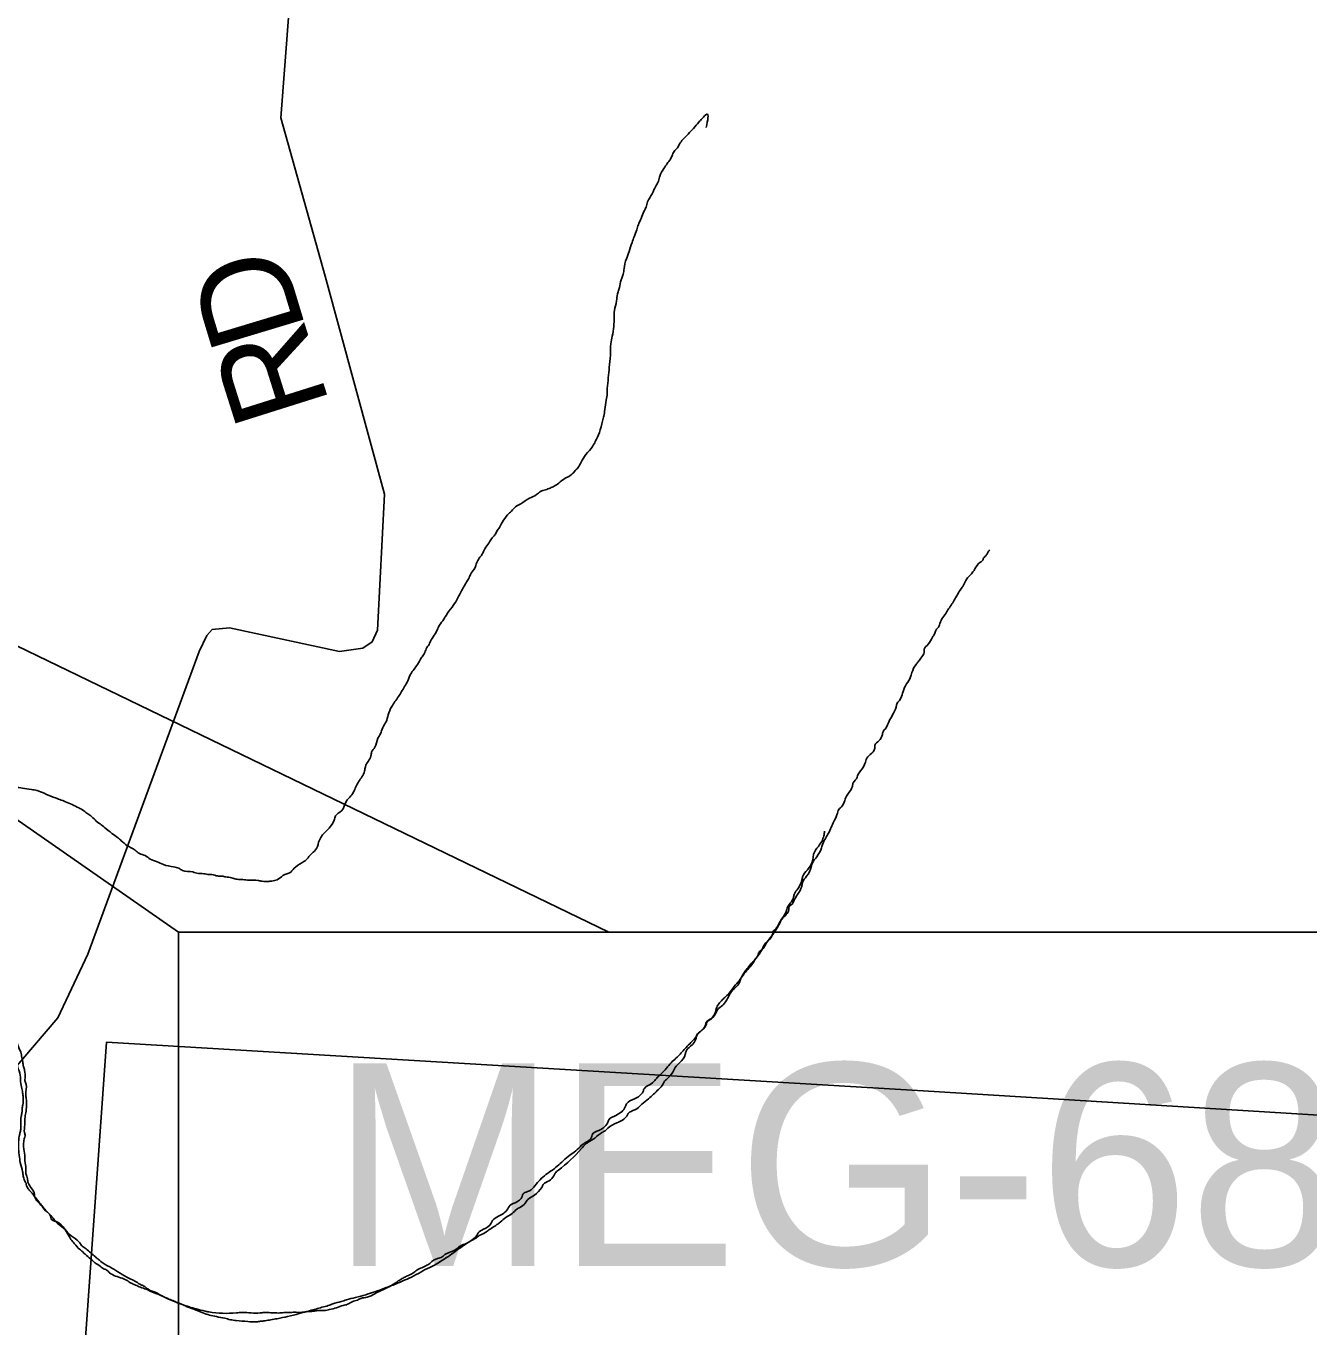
# Model space of a CAD drawing. Extents: x -15 to 405, y -40 to 87.
# Drawn here: x 5.103 to 5.862, y 16.636 to 17.407 of the extents above; entities that cross this region are included whole.
import ezdxf

# ---------------------------------------------------------------- set-up
doc = ezdxf.new("R2010")
doc.units = 0
for name, color, linetype in [('GM_P_State_Location', 7, 'Continuous'), ('GM_X_Adjacent_County', 7, 'Continuous'), ('GM_X_Adjacent_County_Text', 7, 'Continuous'), ('GM_X_Airport_Location_Class_2', 7, 'Continuous'), ('GM_X_Minor_River', 7, 'Continuous'), ('GM_X_Township', 7, 'Continuous')]:
    doc.layers.add(name, color=color, linetype=linetype)

msp = doc.modelspace()

# ---------------------------------------------------------------- linework, layer by layer
at = {"layer": 'GM_P_State_Location'}
msp.add_lwpolyline([(4.89566, 16.45119), (4.92556, 16.51497), (5.0014, 16.68063), (5.04391, 16.72434), (5.0716, 16.7612), (5.12131, 16.81934), (5.13914, 16.85696), (5.2051, 17.03628), (5.20965, 17.04578), (5.21268, 17.0492), (5.22294, 17.05035), (5.28827, 17.03633), (5.30193, 17.03824), (5.30763, 17.04204), (5.31066, 17.04888), (5.31479, 17.12941), (5.27976, 17.25853), (5.2535, 17.35234), (5.25839, 17.41691)], dxfattribs=at)
at = {"layer": 'GM_X_Adjacent_County'}
for points in [[(5.19285, 16.86992), (4.61361, 17.27343), (5.44781, 16.86992)], [(5.19285, 16.58992), (6.44286, 16.58992), (6.44286, 16.86992), (5.19285, 16.86992)]]:
    msp.add_lwpolyline(points, close=True, dxfattribs=at)
at = {"layer": 'GM_X_Adjacent_County_Text'}
for points in [[(5.32873, 17.01885), (5.33038, 17.02297), (5.33436, 17.02854), (5.33677, 17.03264), (5.33837, 17.03487), (5.33961, 17.03787), (5.34121, 17.04047), (5.34244, 17.04309), (5.34484, 17.04681), (5.34605, 17.04905), (5.34728, 17.05167), (5.35005, 17.05538), (5.35127, 17.05762), (5.35484, 17.06244), (5.35765, 17.06691), (5.35927, 17.06989), (5.36169, 17.07437), (5.3637, 17.07773), (5.36491, 17.07996), (5.36614, 17.08258), (5.36853, 17.08592), (5.36938, 17.08856), (5.37099, 17.09154), (5.37258, 17.09377), (5.37421, 17.09714), (5.3766, 17.10048), (5.37821, 17.10308), (5.38018, 17.1053), (5.38139, 17.10754), (5.38298, 17.10976), (5.3846, 17.11275), (5.38779, 17.1172), (5.39013, 17.11941), (5.3925, 17.12199), (5.39559, 17.12378), (5.40064, 17.12704), (5.40488, 17.12918), (5.40722, 17.131), (5.41029, 17.13204), (5.41299, 17.13309), (5.4153, 17.13415), (5.41802, 17.13596), (5.42191, 17.13887), (5.42461, 17.1403), (5.42735, 17.14287), (5.42933, 17.14509), (5.43134, 17.14844), (5.43414, 17.15291), (5.43809, 17.15771), (5.43971, 17.1607), (5.44216, 17.16594), (5.44391, 17.17272), (5.44476, 17.17573), (5.44527, 17.17952), (5.44622, 17.18518), (5.44672, 17.18896), (5.44682, 17.192), (5.44741, 17.19844), (5.44799, 17.2045), (5.44861, 17.2117), (5.44884, 17.21853), (5.44975, 17.22306), (5.45088, 17.23442), (5.45101, 17.23822), (5.45234, 17.24388), (5.45285, 17.24804), (5.4537, 17.25067), (5.45461, 17.2552), (5.45627, 17.25971), (5.45677, 17.26311), (5.45809, 17.26876), (5.45976, 17.27327), (5.46145, 17.27853), (5.4627, 17.28191), (5.46436, 17.28603), (5.46522, 17.28904), (5.46686, 17.29279), (5.46852, 17.29692), (5.46974, 17.29953), (5.4706, 17.30254), (5.47342, 17.30739), (5.47546, 17.31188), (5.47708, 17.31487), (5.47794, 17.31788), (5.48037, 17.32236), (5.48236, 17.32533), (5.48396, 17.32756), (5.48517, 17.3298), (5.48639, 17.33242), (5.48837, 17.33463), (5.48958, 17.33687), (5.49156, 17.33947), (5.49785, 17.3461), (5.50101, 17.34979), (5.50299, 17.35201), (5.50573, 17.35458), (5.50546, 17.34661)], [(5.61988, 17.0073), (5.6211, 17.00954), (5.62237, 17.01368), (5.6248, 17.01815), (5.62683, 17.02227), (5.62726, 17.02377), (5.6297, 17.02863), (5.63089, 17.03011), (5.63248, 17.03234), (5.63449, 17.03569), (5.63455, 17.03759), (5.63693, 17.04055), (5.63934, 17.04465), (5.64054, 17.04651), (5.64138, 17.04876), (5.64336, 17.05136), (5.64379, 17.05286), (5.64781, 17.05957), (5.64941, 17.06218), (5.65141, 17.06515), (5.65222, 17.06664), (5.65382, 17.06925), (5.65583, 17.0726), (5.65742, 17.07483), (5.65985, 17.07931), (5.66143, 17.08116), (5.6634, 17.08337), (5.6646, 17.08523), (5.66738, 17.08894), (5.66893, 17.09003), (5.66974, 17.09152), (5.67132, 17.09337), (5.67213, 17.09486), (5.67332, 17.09634)], [(5.02697, 17.03113), (5.02759, 17.02693), (5.02782, 17.02236), (5.02913, 17.01624), (5.02907, 17.01434), (5.02969, 17.01014), (5.03002, 17.00861), (5.03064, 17.00441), (5.03097, 17.00288), (5.03159, 16.99868), (5.03153, 16.99678), (5.03181, 16.99373), (5.03241, 16.98915), (5.03236, 16.98763), (5.03303, 16.98495), (5.03366, 16.98113), (5.03355, 16.97772), (5.03417, 16.97351), (5.03412, 16.972), (5.03477, 16.96856), (5.03468, 16.9659), (5.03567, 16.96131), (5.03586, 16.9556), (5.03655, 16.95368), (5.03721, 16.95062), (5.03818, 16.94565), (5.0385, 16.94374), (5.03917, 16.94105), (5.03982, 16.93761), (5.04184, 16.92995), (5.04217, 16.92842), (5.04317, 16.9242), (5.0435, 16.92267), (5.04456, 16.92035), (5.0456, 16.91728), (5.04627, 16.9146), (5.04692, 16.91154), (5.04688, 16.91002), (5.04794, 16.9077), (5.0493, 16.9031), (5.04962, 16.90119), (5.05102, 16.89772), (5.05238, 16.89274), (5.05268, 16.89045), (5.05448, 16.88735), (5.05624, 16.88311), (5.05656, 16.88158), (5.05801, 16.87925), (5.05941, 16.87579), (5.06046, 16.87309), (5.06188, 16.87001), (5.06295, 16.86807), (5.06365, 16.86615), (5.06471, 16.86383), (5.06538, 16.86115), (5.06717, 16.85805), (5.06822, 16.85536), (5.07075, 16.85147), (5.07213, 16.84725), (5.0754, 16.84296), (5.07717, 16.8391), (5.08007, 16.83482), (5.08184, 16.83096), (5.08364, 16.82787), (5.08542, 16.82439), (5.08537, 16.82287), (5.08718, 16.82015), (5.08893, 16.81591), (5.08888, 16.81439), (5.09034, 16.81245), (5.09175, 16.80936), (5.09279, 16.80628), (5.09421, 16.8032), (5.09416, 16.80168), (5.09523, 16.79974), (5.09626, 16.79629), (5.0969, 16.79285), (5.09791, 16.78902), (5.09927, 16.78403), (5.09922, 16.78251), (5.09984, 16.77831), (5.10048, 16.77487), (5.10077, 16.7722), (5.10062, 16.76765), (5.10017, 16.76538), (5.10009, 16.76311), (5.09964, 16.76084), (5.09939, 16.75325), (5.09893, 16.75099), (5.09849, 16.7491), (5.0982, 16.74037), (5.09849, 16.7377), (5.09911, 16.7335), (5.10045, 16.72814), (5.10077, 16.72623), (5.10144, 16.72354), (5.1025, 16.72123)], [(5.03238, 16.98758), (5.0304, 16.9858), (5.03267, 16.98534), (5.03492, 16.98451), (5.03718, 16.98406), (5.03943, 16.98322), (5.04282, 16.98235), (5.04507, 16.98151), (5.04767, 16.97991), (5.05064, 16.97791), (5.05323, 16.97592), (5.05581, 16.97356), (5.06026, 16.97037), (5.06584, 16.96677), (5.06807, 16.96555), (5.07068, 16.96395), (5.07292, 16.96274), (5.07815, 16.96028), (5.0804, 16.95945), (5.08303, 16.9586), (5.08528, 16.95777), (5.08792, 16.9573), (5.09094, 16.95682), (5.0932, 16.95636), (5.09622, 16.95588), (5.10038, 16.95536), (5.10566, 16.95443), (5.10906, 16.95394), (5.11318, 16.95228), (5.11918, 16.9498), (5.12593, 16.9473), (5.13378, 16.94362), (5.13601, 16.9424), (5.13861, 16.94042), (5.14083, 16.93882), (5.14341, 16.93646), (5.14637, 16.93408), (5.14896, 16.9321), (5.1534, 16.92853), (5.15673, 16.92614), (5.15895, 16.92417), (5.16227, 16.92139), (5.16711, 16.91857), (5.1697, 16.91659), (5.17308, 16.91534), (5.17605, 16.91334), (5.18017, 16.91168), (5.18391, 16.91004), (5.18994, 16.9087), (5.19295, 16.90784), (5.19519, 16.90662), (5.20123, 16.90566), (5.20462, 16.90479), (5.20689, 16.90471), (5.21029, 16.90422), (5.21257, 16.90415), (5.21595, 16.90328), (5.21861, 16.90319), (5.22087, 16.90273), (5.22427, 16.90224), (5.2269, 16.90139), (5.22993, 16.90129), (5.23371, 16.90079), (5.24016, 16.90057), (5.24242, 16.90012), (5.24584, 16.9), (5.24812, 16.90031), (5.25118, 16.90097), (5.25468, 16.90351), (5.25931, 16.90564), (5.26206, 16.90859), (5.26711, 16.91184), (5.27182, 16.91662), (5.27457, 16.91957), (5.27625, 16.92446), (5.285, 16.93633), (5.28584, 16.93896), (5.28936, 16.94188), (5.2922, 16.94749), (5.29497, 16.95082), (5.29656, 16.95304), (5.2978, 16.95604), (5.30141, 16.962), (5.30304, 16.96537), (5.30351, 16.96801), (5.30676, 16.97436), (5.30721, 16.97663), (5.30921, 16.9796), (5.3109, 16.98486), (5.3125, 16.98747), (5.31377, 16.99123), (5.31577, 16.99458), (5.31705, 16.99872), (5.31911, 17.00359), (5.3231, 17.00953), (5.32672, 17.0155), (5.32873, 17.01885)], [(5.408, 16.7187), (5.40882, 16.72057), (5.41231, 16.72274), (5.41506, 16.72569), (5.41587, 16.72718), (5.41783, 16.72902), (5.43154, 16.74186), (5.43391, 16.74444), (5.43546, 16.74553), (5.43934, 16.74806), (5.44363, 16.75134), (5.44556, 16.75241), (5.44713, 16.75388), (5.45255, 16.75712), (5.45837, 16.76111), (5.45918, 16.7626), (5.46305, 16.76475), (5.46733, 16.76803), (5.47124, 16.77132), (5.47711, 16.77683), (5.47988, 16.78015), (5.48069, 16.78165), (5.48304, 16.78385), (5.48623, 16.78831), (5.48703, 16.7898), (5.48979, 16.79275), (5.49299, 16.79758), (5.49343, 16.79946), (5.49618, 16.80241), (5.49938, 16.80725), (5.49982, 16.80913), (5.50217, 16.81133), (5.50495, 16.81504), (5.50538, 16.81655), (5.50811, 16.81874), (5.5109, 16.82282), (5.51134, 16.82471), (5.51493, 16.82991), (5.51689, 16.83175), (5.51965, 16.83469), (5.52282, 16.83877), (5.52559, 16.8421), (5.52797, 16.84544), (5.53074, 16.84877), (5.53312, 16.85173), (5.53472, 16.85433), (5.53592, 16.85619), (5.53635, 16.8577), (5.53831, 16.85953), (5.5407, 16.86287), (5.5427, 16.86585), (5.54548, 16.86955), (5.54949, 16.87626), (5.5503, 16.87775), (5.55428, 16.88332), (5.55433, 16.88484), (5.55629, 16.88667), (5.5575, 16.88891), (5.55951, 16.89227), (5.56195, 16.89713), (5.56241, 16.89939), (5.56481, 16.90311), (5.56765, 16.90872), (5.5685, 16.91135), (5.57089, 16.91469), (5.57372, 16.91992), (5.57415, 16.92142), (5.57579, 16.92517), (5.5766, 16.92666), (5.5782, 16.92927), (5.57984, 16.93301), (5.58148, 16.93638), (5.58313, 16.9405), (5.58356, 16.94201), (5.58553, 16.94422), (5.58755, 16.94796), (5.58798, 16.94946), (5.59079, 16.95393), (5.59201, 16.95655), (5.59245, 16.95843), (5.59484, 16.96177), (5.59527, 16.96328), (5.59686, 16.96551), (5.59969, 16.97073), (5.60012, 16.97224), (5.6025, 16.9752), (5.60528, 16.97891), (5.60534, 16.9808), (5.6077, 16.98339), (5.60973, 16.98712), (5.61016, 16.98862), (5.61175, 16.99085), (5.61378, 16.99496), (5.61581, 16.9987), (5.61785, 17.00319), (5.61829, 17.00507), (5.61988, 17.0073)], [(5.27427, 16.64676), (5.27772, 16.64778), (5.28155, 16.6488), (5.28425, 16.64985), (5.28923, 16.6512), (5.2923, 16.65224), (5.29766, 16.65359), (5.30379, 16.65528), (5.30916, 16.657), (5.31492, 16.65909), (5.31838, 16.6605), (5.32145, 16.66153), (5.32454, 16.66295), (5.32954, 16.66507), (5.34036, 16.67079), (5.34538, 16.67328), (5.34926, 16.67581), (5.35275, 16.67798), (5.35664, 16.68089), (5.36091, 16.68379), (5.36557, 16.68705), (5.36948, 16.69034), (5.37029, 16.69183), (5.3734, 16.69401), (5.37807, 16.69766), (5.37888, 16.69915), (5.38238, 16.70169), (5.38784, 16.70607), (5.38865, 16.70756), (5.39214, 16.70973), (5.39644, 16.71339), (5.39686, 16.71489), (5.39957, 16.71632), (5.40623, 16.72256), (5.41326, 16.72841), (5.41715, 16.73132), (5.42067, 16.73462), (5.42458, 16.73791), (5.42808, 16.74045), (5.43161, 16.74376), (5.43355, 16.74521), (5.43746, 16.7485), (5.43789, 16.75001), (5.44177, 16.75254), (5.44685, 16.75693), (5.44767, 16.75881), (5.45232, 16.76169), (5.45741, 16.76646), (5.45823, 16.76833), (5.46288, 16.77122), (5.46796, 16.77561), (5.46878, 16.77748), (5.47189, 16.77966), (5.47501, 16.78222), (5.47659, 16.78406), (5.47934, 16.78663), (5.4817, 16.78921), (5.48328, 16.79106), (5.48603, 16.79401), (5.48878, 16.79658), (5.4935, 16.80174), (5.49901, 16.80764), (5.50178, 16.81097), (5.50533, 16.81503), (5.50576, 16.81653), (5.50849, 16.81872), (5.51127, 16.82243), (5.51208, 16.82392), (5.51521, 16.82686), (5.5188, 16.83206), (5.52001, 16.8343), (5.52514, 16.84021), (5.52598, 16.84246), (5.52959, 16.84842), (5.53433, 16.85396), (5.53872, 16.86028), (5.53954, 16.86215), (5.5419, 16.86473), (5.54469, 16.86882), (5.54512, 16.87033), (5.54709, 16.87254), (5.54911, 16.87628), (5.55111, 16.87925), (5.55314, 16.88336), (5.55357, 16.88486), (5.55517, 16.88709), (5.55719, 16.89083), (5.55763, 16.89271), (5.55963, 16.89568), (5.56208, 16.90092), (5.56252, 16.90281), (5.56531, 16.90689), (5.56856, 16.91325), (5.56904, 16.91627), (5.57185, 16.92074), (5.57509, 16.92709), (5.57556, 16.92974)], [(5.06234, 16.86125), (5.06303, 16.85895), (5.06446, 16.85624), (5.06587, 16.85315), (5.06841, 16.84965), (5.07056, 16.84578), (5.07088, 16.84387), (5.07346, 16.8415), (5.07668, 16.8357), (5.07777, 16.83414), (5.07922, 16.83219), (5.0803, 16.83026), (5.08138, 16.8287), (5.08283, 16.82637), (5.08503, 16.82402), (5.08684, 16.8213), (5.08866, 16.81896), (5.09154, 16.81431), (5.09261, 16.81237), (5.09407, 16.81042), (5.09515, 16.80887), (5.09586, 16.80732), (5.09729, 16.80462), (5.09762, 16.80308), (5.09938, 16.79885), (5.10004, 16.79578), (5.10068, 16.79235), (5.101, 16.79043), (5.10168, 16.78813), (5.10191, 16.78356), (5.10186, 16.78205), (5.10254, 16.77974), (5.10235, 16.77405), (5.10264, 16.77138), (5.10237, 16.76303), (5.10188, 16.75963), (5.1018, 16.75735), (5.10175, 16.75583), (5.1016, 16.75128), (5.10191, 16.74937), (5.10149, 16.74786), (5.10127, 16.74141), (5.10188, 16.73683), (5.1018, 16.73455), (5.10241, 16.72997), (5.10234, 16.72769), (5.10302, 16.72539), (5.10335, 16.72386), (5.10366, 16.72195), (5.10618, 16.71769), (5.10725, 16.71575), (5.10756, 16.71346), (5.11192, 16.70762), (5.11301, 16.70606), (5.11704, 16.70175), (5.11737, 16.70022), (5.12035, 16.6986), (5.12911, 16.68805), (5.1313, 16.68532), (5.13423, 16.68218), (5.13608, 16.6806), (5.13902, 16.67784), (5.14271, 16.67468), (5.14419, 16.67349), (5.14569, 16.67268), (5.14828, 16.6707), (5.15015, 16.66987), (5.15199, 16.66829), (5.15948, 16.665), (5.16209, 16.66378), (5.1647, 16.66217), (5.16731, 16.66094), (5.17031, 16.65971), (5.17369, 16.65845), (5.17743, 16.65681), (5.18155, 16.65515), (5.18604, 16.6531), (5.18978, 16.65146), (5.19428, 16.64979), (5.19689, 16.64857), (5.19914, 16.64773), (5.20327, 16.64607), (5.21114, 16.64315), (5.21529, 16.64226), (5.22019, 16.64133), (5.22358, 16.64046), (5.22698, 16.63997), (5.23379, 16.63936), (5.2391, 16.63919), (5.24139, 16.63949), (5.24406, 16.63978), (5.24749, 16.64043), (5.25131, 16.64106), (5.25743, 16.64238), (5.26431, 16.64405), (5.27044, 16.64575), (5.27427, 16.64676)], [(5.1025, 16.72123), (5.10283, 16.7197), (5.10427, 16.71737), (5.10574, 16.7158), (5.10719, 16.71385), (5.11011, 16.71034), (5.11193, 16.708), (5.11412, 16.70526), (5.11559, 16.7037), (5.11852, 16.70056), (5.12034, 16.69822), (5.12477, 16.69465), (5.12807, 16.69112), (5.13289, 16.68754), (5.13436, 16.68598), (5.13581, 16.68403), (5.13804, 16.68243), (5.14357, 16.67769), (5.14505, 16.6765), (5.1469, 16.67492), (5.15211, 16.67171), (5.15695, 16.66889), (5.16216, 16.66567), (5.16552, 16.66404), (5.1685, 16.66242), (5.17036, 16.66122), (5.17223, 16.6604), (5.17446, 16.65881), (5.17669, 16.65759), (5.17894, 16.65676), (5.18267, 16.65474), (5.18716, 16.65269), (5.19016, 16.65145), (5.19277, 16.65022), (5.19502, 16.64939), (5.20329, 16.64683), (5.20856, 16.64552), (5.21082, 16.64506), (5.22713, 16.64452), (5.23056, 16.64479), (5.24117, 16.64444), (5.24346, 16.64474), (5.24574, 16.64467), (5.24915, 16.64455), (5.25294, 16.64443), (5.25599, 16.64471), (5.25864, 16.64462), (5.26131, 16.64491), (5.26586, 16.64476), (5.26776, 16.64508), (5.27119, 16.64534), (5.27386, 16.64563), (5.2769, 16.64591), (5.27918, 16.64584), (5.28224, 16.6465), (5.28645, 16.6475), (5.29029, 16.64889), (5.29297, 16.64956), (5.2949, 16.65064), (5.29644, 16.65134), (5.29951, 16.65238), (5.30106, 16.65309), (5.30449, 16.65374), (5.30912, 16.65586), (5.31916, 16.66085), (5.32303, 16.66338), (5.32536, 16.66482), (5.32729, 16.6659), (5.32961, 16.66696), (5.33231, 16.66839), (5.33465, 16.67022), (5.33619, 16.67093), (5.33927, 16.67234), (5.3416, 16.67379), (5.34433, 16.67598), (5.34625, 16.67667), (5.34894, 16.67772), (5.35128, 16.67954), (5.3532, 16.68024), (5.35706, 16.68201), (5.36056, 16.68456), (5.36248, 16.68525), (5.36712, 16.68776), (5.36905, 16.68884), (5.371, 16.69029), (5.37447, 16.69207), (5.37603, 16.69316), (5.38146, 16.69678), (5.38341, 16.69824), (5.38692, 16.70116), (5.39041, 16.70333), (5.39315, 16.70589), (5.39509, 16.70697), (5.39821, 16.70953), (5.3998, 16.71175), (5.40368, 16.71429), (5.408, 16.7187)]]:
    msp.add_spline(points, degree=3, dxfattribs=at)
at = {"layer": 'GM_X_Airport_Location_Class_2'}
msp.add_lwpolyline([(5.63387, 16.77601), (6.15699, 16.74379), (6.14986, 16.6258), (6.12237, 16.20392), (6.09129, 15.72442), (5.0777, 15.78671), (5.15021, 16.80486)], close=True, dxfattribs=at)

# ---------------------------------------------------------------- texts
at = {"layer": 'GM_X_Minor_River'}
for s, rotation, p in [('D', 106.81298, (5.26866, 17.22686)), ('R', 107.52707, (5.28266, 17.18254))]:
    msp.add_text(s, height=0.05682, rotation=rotation, dxfattribs=at).set_placement(p)
at = {"layer": 'GM_X_Township'}
msp.add_text('MEG-689-1.87', height=0.12, dxfattribs=at).set_placement((5.28316, 16.67222))

doc.saveas('drawing.dxf')
